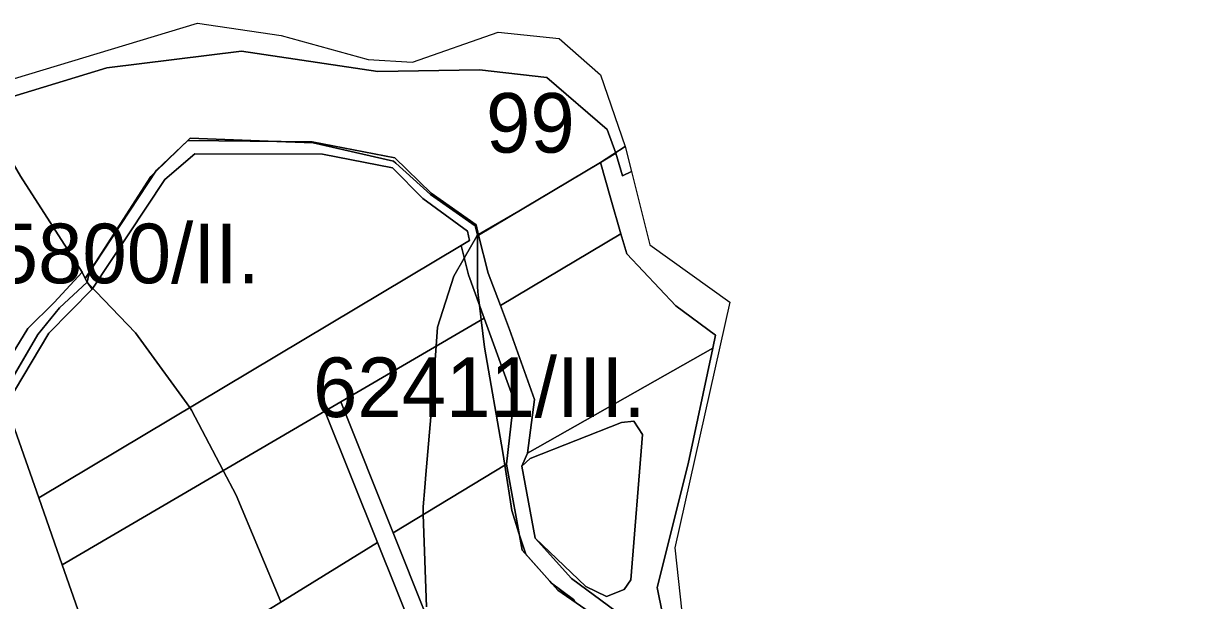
# Model space of a CAD drawing. Extents: x -522079 to -518792, y -1142400 to -1139961.
# Drawn here: x -520985.3 to -520693.7, y -1140238.4 to -1140093 of the extents above; entities that cross this region are included whole.
import ezdxf

# ---------------------------------------------------------------- set-up
doc = ezdxf.new("R2010")
doc.units = 0
for name, color, linetype in [('Bonity', 7, 'Continuous'), ('Hranice parcel', 7, 'Continuous'), ('Parcelní čísla', 7, 'Continuous'), ('Poz předměty', 7, 'Continuous'), ('Vnitřní kresba', 7, 'Continuous'), ('Značky bodu BP', 7, 'Continuous'), ('Značky kultur', 7, 'Continuous')]:
    doc.layers.add(name, color=color, linetype=linetype)

msp = doc.modelspace()

# ---------------------------------------------------------------- linework, layer by layer
at = {"layer": 'Bonity'}
msp.add_lwpolyline([(-520999.73, -1140195.29), (-521008.55, -1140178.79), (-521045.99, -1140153.16), (-520994.7, -1140116.62), (-520985.99, -1140131.48), (-520970.51, -1140155.67), (-520977.56, -1140163.28), (-520984.14, -1140169.84)], close=True, dxfattribs=at)
at = {"layer": 'Hranice parcel'}
msp.add_lwpolyline([(-520985.99, -1140131.48), (-520994.7, -1140116.62), (-520996.26, -1140113.95), (-520964.33, -1140104.24), (-520930.39, -1140100.03), (-520896.13, -1140105.14), (-520870.57, -1140104.77), (-520853.61, -1140106.69), (-520838.47, -1140119.76), (-520836.28, -1140125.74), (-520840.13, -1140128.04), (-520870.79, -1140146.36), (-520871.38, -1140143.8), (-520882.74, -1140135.78), (-520891.9, -1140126.87), (-520912.67, -1140122.89), (-520943.89, -1140122.58), (-520951.79, -1140130), (-520969.72, -1140157.28), (-520970.51, -1140155.67)], close=True, dxfattribs=at)
msp.add_lwpolyline([(-520989.57, -1140189.1), (-520981.4, -1140212.45), (-520975.5, -1140229.32), (-520963.03, -1140264.99), (-520942.5, -1140323.7), (-520932.27, -1140351.12), (-520925.04, -1140368.05), (-520924.44, -1140369.44), (-520915.77, -1140387.04), (-520907.24, -1140403.74), (-520902.19, -1140412.67), (-520887.82, -1140434.78), (-520876.46, -1140450.75), (-520851.49, -1140482.48), (-520837.71, -1140499.35), (-520813.81, -1140528.62)], dxfattribs=at)
at = {"layer": 'Parcelní čísla'}
for points in [[(-520875.21, -1140149), (-520981.4, -1140212.45), (-520989.57, -1140189.1), (-520978.85, -1140171.05), (-520967.99, -1140160), (-520949.73, -1140132.35), (-520942.17, -1140125.91), (-520910.05, -1140126.02), (-520892.49, -1140129.42), (-520884.78, -1140137.14), (-520873.63, -1140145.32), (-520873.12, -1140147.75)], [(-520873.34, -1140156.37), (-520869.38, -1140167.25), (-520905.41, -1140188.32), (-520909.48, -1140190.7), (-520975.5, -1140229.32), (-520981.4, -1140212.45), (-520875.21, -1140149)], [(-520869.38, -1140167.25), (-520861.9, -1140187.8), (-520863.77, -1140204.01), (-520892.27, -1140221.28), (-520905.41, -1140188.32)], [(-520896.25, -1140223.69), (-520963.03, -1140264.99), (-520975.5, -1140229.32), (-520909.48, -1140190.7)], [(-520863.77, -1140204.01), (-520859.87, -1140225.61), (-520850.88, -1140235.71), (-520840.6, -1140242.88), (-520840.04, -1140256.81), (-520835.3, -1140267.04), (-520827.93, -1140275.18), (-520828.6, -1140285.19), (-520817.67, -1140300.36), (-520822.46, -1140303.46), (-520852.13, -1140321.93), (-520892.27, -1140221.28)], [(-520963.03, -1140264.99), (-520896.25, -1140223.69), (-520855.89, -1140324.19), (-520893.13, -1140348.26), (-520925.04, -1140368.05), (-520932.27, -1140351.12), (-520942.5, -1140323.7)]]:
    msp.add_lwpolyline(points, close=True, dxfattribs=at)
msp.add_lwpolyline([(-520722.28, -1140522.46), (-520749.72, -1140487.1), (-520772.84, -1140457.31), (-520777.25, -1140451.62), (-520784.75, -1140439.67), (-520830.07, -1140367.42), (-520853.68, -1140329.78), (-520855.89, -1140324.19), (-520896.25, -1140223.69), (-520909.48, -1140190.7), (-520905.41, -1140188.32), (-520892.27, -1140221.28), (-520852.13, -1140321.93), (-520849.95, -1140326.96), (-520781.06, -1140437.3), (-520773.55, -1140448.4), (-520769.04, -1140453.82), (-520745.68, -1140484.57), (-520717.71, -1140519.42), (-520693.7, -1140549.35)], dxfattribs=at)
at = {"layer": 'Poz předměty'}
msp.add_lwpolyline([(-520831.58, -1140264.76), (-520835.7, -1140256.78), (-520836.21, -1140241.05), (-520847.4, -1140232.82), (-520856.59, -1140222.67), (-520843.85, -1140234.81), (-520838.62, -1140237.3), (-520834.17, -1140235.54), (-520832.49, -1140233.14), (-520829.57, -1140196.57), (-520831.74, -1140193.15), (-520834.84, -1140193.48), (-520857.8, -1140202.58), (-520859.91, -1140204.51), (-520858.48, -1140201.26), (-520811.93, -1140174.77), (-520818.11, -1140203.91), (-520825.87, -1140235.03), (-520821.91, -1140254.48), (-520810.93, -1140259.32), (-520828.22, -1140268.46)], close=True, dxfattribs=at)
at = {"layer": 'Vnitřní kresba'}
for points in [[(-520840.13, -1140106.03), (-520833.95, -1140124.09), (-520832.38, -1140130.38), (-520834.57, -1140131.44), (-520836.28, -1140125.74), (-520838.47, -1140119.76), (-520853.61, -1140106.69), (-520870.57, -1140104.77), (-520896.13, -1140105.14), (-520930.39, -1140100.03), (-520964.33, -1140104.24), (-520996.26, -1140113.95), (-520998.41, -1140110.24), (-520941.45, -1140093.01), (-520920.41, -1140096.1), (-520898.59, -1140102.13), (-520887.39, -1140102.82), (-520865.88, -1140095.27), (-520850.56, -1140096.88)], [(-520829.57, -1140196.57), (-520832.49, -1140233.14), (-520834.17, -1140235.54), (-520838.62, -1140237.3), (-520843.85, -1140234.81), (-520856.59, -1140222.67), (-520859.91, -1140204.51), (-520857.8, -1140202.58), (-520834.84, -1140193.48), (-520831.74, -1140193.15)]]:
    msp.add_lwpolyline(points, close=True, dxfattribs=at)
for points in [[(-520840.6, -1140242.88), (-520850.88, -1140235.71), (-520859.87, -1140225.61), (-520863.77, -1140204.01), (-520861.9, -1140187.8), (-520869.38, -1140167.25), (-520873.34, -1140156.37), (-520875.21, -1140149), (-520873.12, -1140147.75), (-520873.63, -1140145.32), (-520884.78, -1140137.14), (-520892.49, -1140129.42), (-520910.05, -1140126.02), (-520942.17, -1140125.91), (-520949.73, -1140132.35), (-520967.99, -1140160), (-520969.27, -1140158.18), (-520969.72, -1140157.28), (-520951.79, -1140130), (-520943.89, -1140122.58), (-520912.67, -1140122.89), (-520891.9, -1140126.87), (-520882.74, -1140135.78), (-520871.38, -1140143.8), (-520870.79, -1140146.36), (-520868.43, -1140155.94), (-520865.3, -1140164.1), (-520863, -1140170.11), (-520856.72, -1140187.75), (-520858.48, -1140201.26), (-520859.91, -1140204.51), (-520856.59, -1140222.67), (-520847.4, -1140232.82), (-520836.21, -1140241.05)], [(-520821.91, -1140254.48), (-520825.87, -1140235.03), (-520818.11, -1140203.91), (-520811.93, -1140174.77), (-520811.24, -1140171.54), (-520821.16, -1140164.16), (-520833.53, -1140151.04), (-520834.99, -1140146), (-520837.6, -1140136.97), (-520840.13, -1140128.04), (-520836.28, -1140125.74), (-520834.57, -1140131.44), (-520832.38, -1140130.38), (-520827.76, -1140148.83), (-520807.65, -1140163.22), (-520821.47, -1140225.09), (-520818.83, -1140248.97)], [(-520999.73, -1140195.29), (-520984.14, -1140169.84), (-520977.56, -1140163.28), (-520970.51, -1140155.67), (-520969.72, -1140157.28), (-520969.27, -1140158.18), (-520976.2, -1140164.63), (-520981.64, -1140171.39), (-520997.26, -1140198.03)], [(-520997.26, -1140198.03), (-520981.64, -1140171.39), (-520976.2, -1140164.63), (-520969.27, -1140158.18), (-520967.99, -1140160), (-520978.85, -1140171.05), (-520989.57, -1140189.1)]]:
    msp.add_lwpolyline(points, dxfattribs=at)
at = {"layer": 'Značky bodu BP'}
for points in [[(-520998.41, -1140110.24), (-520941.45, -1140093.01), (-520920.41, -1140096.1), (-520898.59, -1140102.13), (-520887.39, -1140102.82), (-520865.88, -1140095.27), (-520850.56, -1140096.88), (-520840.13, -1140106.03), (-520833.95, -1140124.09), (-520840.13, -1140128.04), (-520860.65, -1140140.3), (-520870.83, -1140146.2), (-520871.09, -1140146.35), (-520871.66, -1140144), (-520882.88, -1140136.16), (-520891.57, -1140128.28), (-520892.21, -1140127.7), (-520912.38, -1140123.16), (-520921.58, -1140122.8), (-520943.31, -1140121.94), (-520946.31, -1140124.85), (-520952.08, -1140130.44), (-520953.23, -1140131.56), (-520968.64, -1140155.63), (-520969.27, -1140158.18), (-520969.72, -1140157.28), (-520970.51, -1140155.67), (-520985.99, -1140131.48)], [(-520920.51, -1140238.69), (-520931.79, -1140211.78), (-520935.01, -1140205.63), (-520943.01, -1140190.38), (-520943.45, -1140189.77), (-520955.71, -1140172.81), (-520957.05, -1140170.96), (-520969.04, -1140158.41), (-520969.27, -1140158.18), (-520968.64, -1140155.63), (-520953.23, -1140131.56), (-520952.08, -1140130.44), (-520946.31, -1140124.85), (-520943.31, -1140121.94), (-520921.58, -1140122.8), (-520912.38, -1140123.16), (-520892.21, -1140127.7), (-520891.57, -1140128.28), (-520882.88, -1140136.16), (-520871.66, -1140144), (-520871.09, -1140146.35), (-520871.25, -1140146.63), (-520874.41, -1140152.14), (-520877.03, -1140156.7), (-520881.13, -1140169.5), (-520881.48, -1140174.33), (-520882.5, -1140188.24), (-520884.08, -1140206.62), (-520884.36, -1140209.88), (-520884.77, -1140214.75), (-520884.7, -1140216.69), (-520883.86, -1140239.89)], [(-520846.54, -1140238.74), (-520846.96, -1140238.06), (-520852.43, -1140233.95), (-520852.92, -1140233.42), (-520858.95, -1140226.65), (-520860.64, -1140221.33), (-520862.45, -1140215.67), (-520864.22, -1140204.28), (-520864.73, -1140201.04), (-520869.28, -1140174.53), (-520870.11, -1140167.68), (-520870.55, -1140164.02), (-520870.87, -1140161.44), (-520871.11, -1140159.45), (-520871.09, -1140146.55), (-520871.09, -1140146.35), (-520870.83, -1140146.2), (-520860.65, -1140140.3), (-520840.13, -1140128.04), (-520833.95, -1140124.09), (-520832.38, -1140130.38), (-520827.76, -1140148.83), (-520807.65, -1140163.22), (-520821.47, -1140225.09), (-520818.83, -1140248.97)], [(-520883.86, -1140239.89), (-520884.7, -1140216.69), (-520884.77, -1140214.75), (-520884.36, -1140209.88), (-520884.08, -1140206.62), (-520882.5, -1140188.24), (-520881.48, -1140174.33), (-520881.13, -1140169.5), (-520877.03, -1140156.7), (-520874.41, -1140152.14), (-520871.25, -1140146.63), (-520871.09, -1140146.35), (-520871.09, -1140146.55), (-520871.11, -1140159.45), (-520870.87, -1140161.44), (-520870.55, -1140164.02), (-520870.11, -1140167.68), (-520869.28, -1140174.53), (-520864.73, -1140201.04), (-520864.22, -1140204.28), (-520862.45, -1140215.67), (-520860.64, -1140221.33), (-520858.95, -1140226.65), (-520852.92, -1140233.42), (-520852.43, -1140233.95), (-520846.96, -1140238.06), (-520846.54, -1140238.74)], [(-520994.97, -1140194.13), (-520981.64, -1140171.39), (-520976.2, -1140164.63), (-520969.27, -1140158.18), (-520969.04, -1140158.41), (-520957.05, -1140170.96), (-520955.71, -1140172.81), (-520943.45, -1140189.77), (-520943.01, -1140190.38), (-520935.01, -1140205.63), (-520931.79, -1140211.78), (-520920.51, -1140238.69)]]:
    msp.add_lwpolyline(points, dxfattribs=at)
msp.add_lwpolyline([(-520969.27, -1140158.18), (-520976.2, -1140164.63), (-520981.64, -1140171.39), (-520994.97, -1140194.13), (-520995.24, -1140194.59), (-520995.41, -1140194.88), (-520996, -1140195.88), (-520997.26, -1140198.03), (-520998.32, -1140199.84), (-520998.6, -1140200.31), (-520999.73, -1140195.29), (-521008.55, -1140178.79), (-521045.99, -1140153.16), (-521044.19, -1140151.88), (-520994.7, -1140116.62), (-520985.99, -1140131.48), (-520970.51, -1140155.67), (-520969.72, -1140157.28)], close=True, dxfattribs=at)
at = {"layer": 'Značky kultur'}
for points in [[(-520870.79, -1140146.36), (-520840.13, -1140128.04), (-520837.6, -1140136.97), (-520834.99, -1140146), (-520865.3, -1140164.1), (-520868.43, -1140155.94)], [(-520811.24, -1140171.54), (-520811.93, -1140174.77), (-520858.48, -1140201.26), (-520856.72, -1140187.75), (-520863, -1140170.11), (-520865.3, -1140164.1), (-520834.99, -1140146), (-520833.53, -1140151.04), (-520821.16, -1140164.16)]]:
    msp.add_lwpolyline(points, close=True, dxfattribs=at)

# ---------------------------------------------------------------- texts
at = {"layer": 'Značky bodu BP'}
for s, rotation, p in [('99', 0, (-520868.93, -1140125.6)), ('35800/II.', 360, (-521003.91, -1140158.47)), ('62411/III.', 0, (-520912.44, -1140192.15))]:
    msp.add_text(s, height=15, rotation=rotation, dxfattribs=at).set_placement(p)

doc.saveas('drawing.dxf')
